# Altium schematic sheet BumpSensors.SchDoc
size A; SheetNumber: roneV11-BumpSensors; SheetTotal: 6
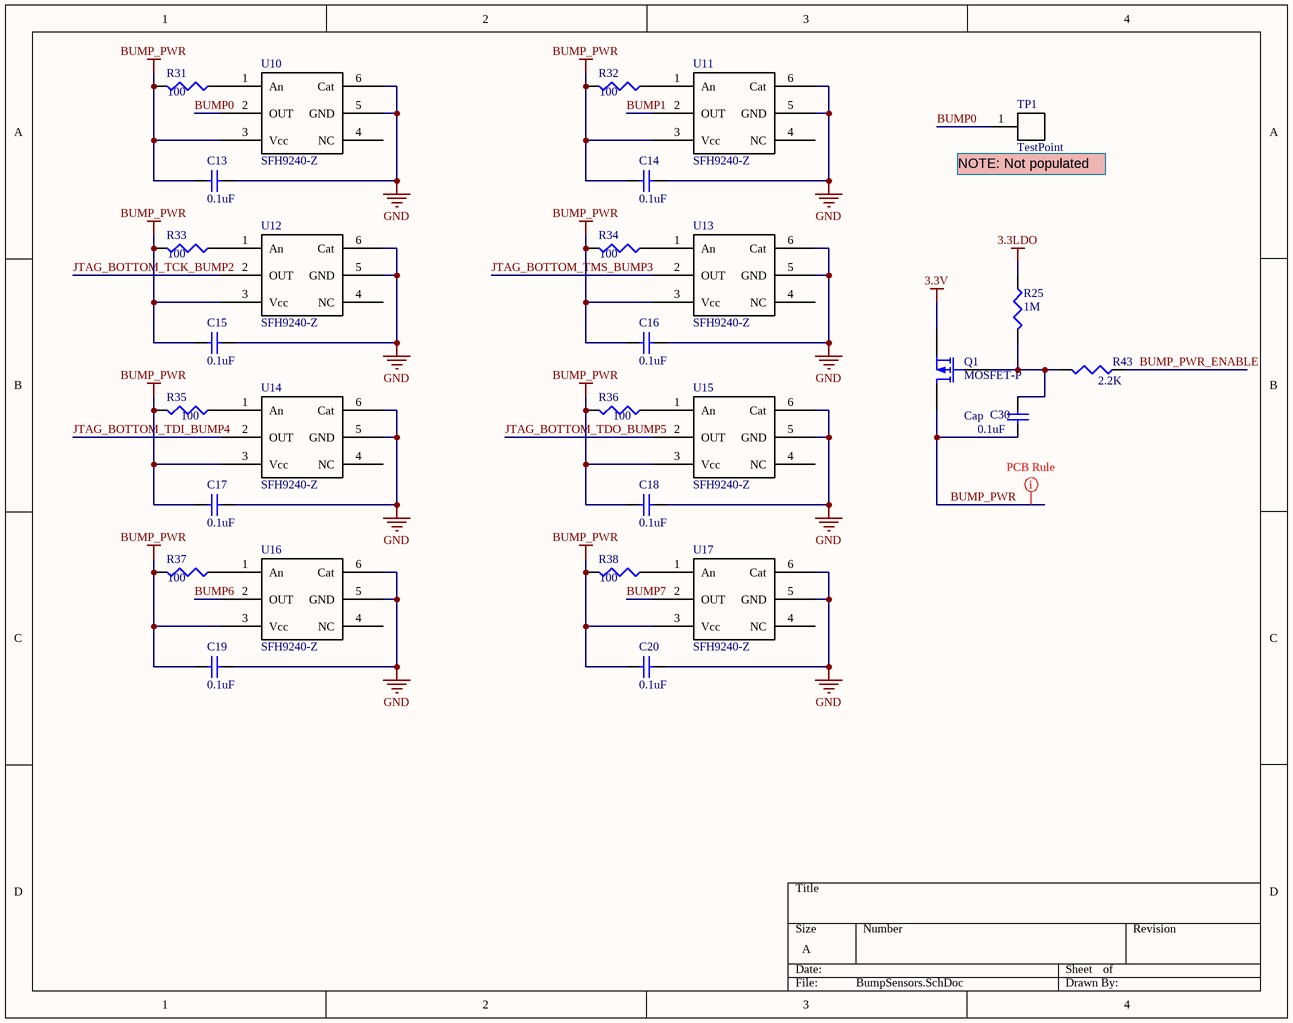
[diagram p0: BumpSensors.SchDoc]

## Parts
C13  value 0.1uF  [CAPC1005L]  (hidden comment: Cap Semi)
C14  value 0.1uF  [CAPC1005L]  (hidden comment: Cap Semi)
C15  value 0.1uF  [CAPC1005L]  (hidden comment: Cap Semi)
C16  value 0.1uF  [CAPC1005L]  (hidden comment: Cap Semi)
C17  value 0.1uF  [CAPC1005L]  (hidden comment: Cap Semi)
C18  value 0.1uF  [CAPC1005L]  (hidden comment: Cap Semi)
C19  value 0.1uF  [CAPC1005L]  (hidden comment: Cap Semi)
C20  value 0.1uF  [CAPC1005L]  (hidden comment: Cap Semi)
C30  Cap  value 0.1uF  [CAPC1005L]
Q1  MOSFET-P  [SOT-23]
R25  value 1M  [J1-0603]  (hidden comment: Res3)
R31  value 100  [RESC1608L]  (hidden comment: Res3)
R32  value 100  [RESC1608L]  (hidden comment: Res3)
R33  value 100  [RESC1608L]  (hidden comment: Res3)
R34  value 100  [RESC1608L]  (hidden comment: Res3)
R35  value 100  [RESC1608L]  (hidden comment: Res3)
R36  value 100  [RESC1608L]  (hidden comment: Res3)
R37  value 100  [RESC1608L]  (hidden comment: Res3)
R38  value 100  [RESC1608L]  (hidden comment: Res3)
R43  value 2.2K  [J1-0603]  (hidden comment: Res3)
TP1  TestPoint  [TestPoint]
U10  SFH9240-Z  [SFH9240-Z]
U11  SFH9240-Z  [SFH9240-Z]
U12  SFH9240-Z  [SFH9240-Z]
U13  SFH9240-Z  [SFH9240-Z]
U14  SFH9240-Z  [SFH9240-Z]
U15  SFH9240-Z  [SFH9240-Z]
U16  SFH9240-Z  [SFH9240-Z]
U17  SFH9240-Z  [SFH9240-Z]

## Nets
3.3LDO: R25.1
3.3V: Q1.2(S)
BUMP_PWR: C13.2 C14.2 C15.2 C16.2 C17.2 C18.2 C19.2 C20.2 C30.2 Q1.3(D) R31.2 R32.2 R33.2 R34.2 R35.2 R36.2 R37.2 R38.2 U10.3(Vcc) U11.3(Vcc) U12.3(Vcc) U13.3(Vcc) U14.3(Vcc) U15.3(Vcc) U16.3(Vcc) U17.3(Vcc)
GND: C13.1 C14.1 C15.1 C16.1 C17.1 C18.1 C19.1 C20.1 U10.5(GND) U10.6(Cat) U11.5(GND) U11.6(Cat) U12.5(GND) U12.6(Cat) U13.5(GND) U13.6(Cat) U14.5(GND) U14.6(Cat) U15.5(GND) U15.6(Cat) U16.5(GND) U16.6(Cat) U17.5(GND) U17.6(Cat)
BUMP0: TP1.1 U10.2(OUT)
BUMP1: U11.2(OUT)
BUMP6: U16.2(OUT)
BUMP7: U17.2(OUT)
BUMP_PWR_ENABLE: R43.1
JTAG_BOTTOM_TCK_BUMP2: U12.2(OUT)
JTAG_BOTTOM_TDI_BUMP4: U14.2(OUT)
JTAG_BOTTOM_TDO_BUMP5: U15.2(OUT)
JTAG_BOTTOM_TMS_BUMP3: U13.2(OUT)
NetC30_1: C30.1 Q1.1(G) R25.2 R43.2
NetR31_1: R31.1 U10.1(An)
NetR32_1: R32.1 U11.1(An)
NetR33_1: R33.1 U12.1(An)
NetR34_1: R34.1 U13.1(An)
NetR35_1: R35.1 U14.1(An)
NetR36_1: R36.1 U15.1(An)
NetR37_1: R37.1 U16.1(An)
NetR38_1: R38.1 U17.1(An)

Not connected (* = marked no-connect by the designer): U10 4(NC); U11 4(NC); U12 4(NC); U13 4(NC); U14 4(NC); U15 4(NC); U16 4(NC); U17 4(NC)

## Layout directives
rule Width Constraint [Pref Width = 15mil    Min Width = 10mil    Max Width = 15mil]: BUMP_PWR

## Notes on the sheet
- (near TP1) NOTE: Not populated

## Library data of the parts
C13-C20 = Cap Semi: Capacitor (Semiconductor SIM Model); Part Number: GRM155R71C104KA88D; Manufacturer: Murata
C30 = Cap: Capacitor; Part Number: GRM155R71C104KA88D; Manufacturer: Murata
Q1 = MOSFET-P: P-Channel MOSFET; Part Number: DMG2301U-7; Manufacturer: Diodes
R25 = Res3: Resistor; Part Number: ERJ-3GEY-J105V; Manufacturer: Panasonic
R31-R38 = Res3: Resistor; Part Number: ERJ-3GEYJ101V; Manufacturer: Panasonic
R43 = Res3: Resistor; Part Number: ERJ-3GEYJ222V; Manufacturer: Panasonic
U10-U17 = SFH9240-Z: Manufacturer: OSRAM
